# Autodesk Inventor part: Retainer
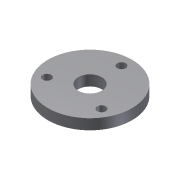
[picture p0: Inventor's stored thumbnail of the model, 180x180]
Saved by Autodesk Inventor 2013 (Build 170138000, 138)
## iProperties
Created: 2009-04
Part Number: Retainer
Document SubType Name: Modeling
Designer: Sham
Density: 1 g/cm^3
Material: Generic
Author: Sham
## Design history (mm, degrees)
sketch "Sketch1"
  geometry: C1 r 100 at (0, 0); C2 r 28 at (0, 0)
  constraints: 2 centre point, 1 coincident
  dimensions: "d0" = 200 diameter of C1; "d1" = 56 diameter of C2
extrude "Extrusion2" new body sketch "Sketch1" distance "d10" = 25; taper "d11" = 0 deg
sketch "Sketch2"
  geometry: C1 r 28 at (0, 0) reference; 1 further point
  constraints: 1 vertical alignment
  dimensions: "d12" = 75 distance of C1.centre point (0, 75)
hole "Hole1" sketch "Sketch2" at (0, 75) diameter "d13" = 20.3; stored, may be unused: countersink angle "d17" = 90 deg, drill point angle "d19" = 118 deg; dims "d14" = 6, "d15" = 4, "d16" = 2, "d18" = 8
pattern_circular "Circular Pattern1" dims angle "d21" = 360 deg
body "Solid2"
